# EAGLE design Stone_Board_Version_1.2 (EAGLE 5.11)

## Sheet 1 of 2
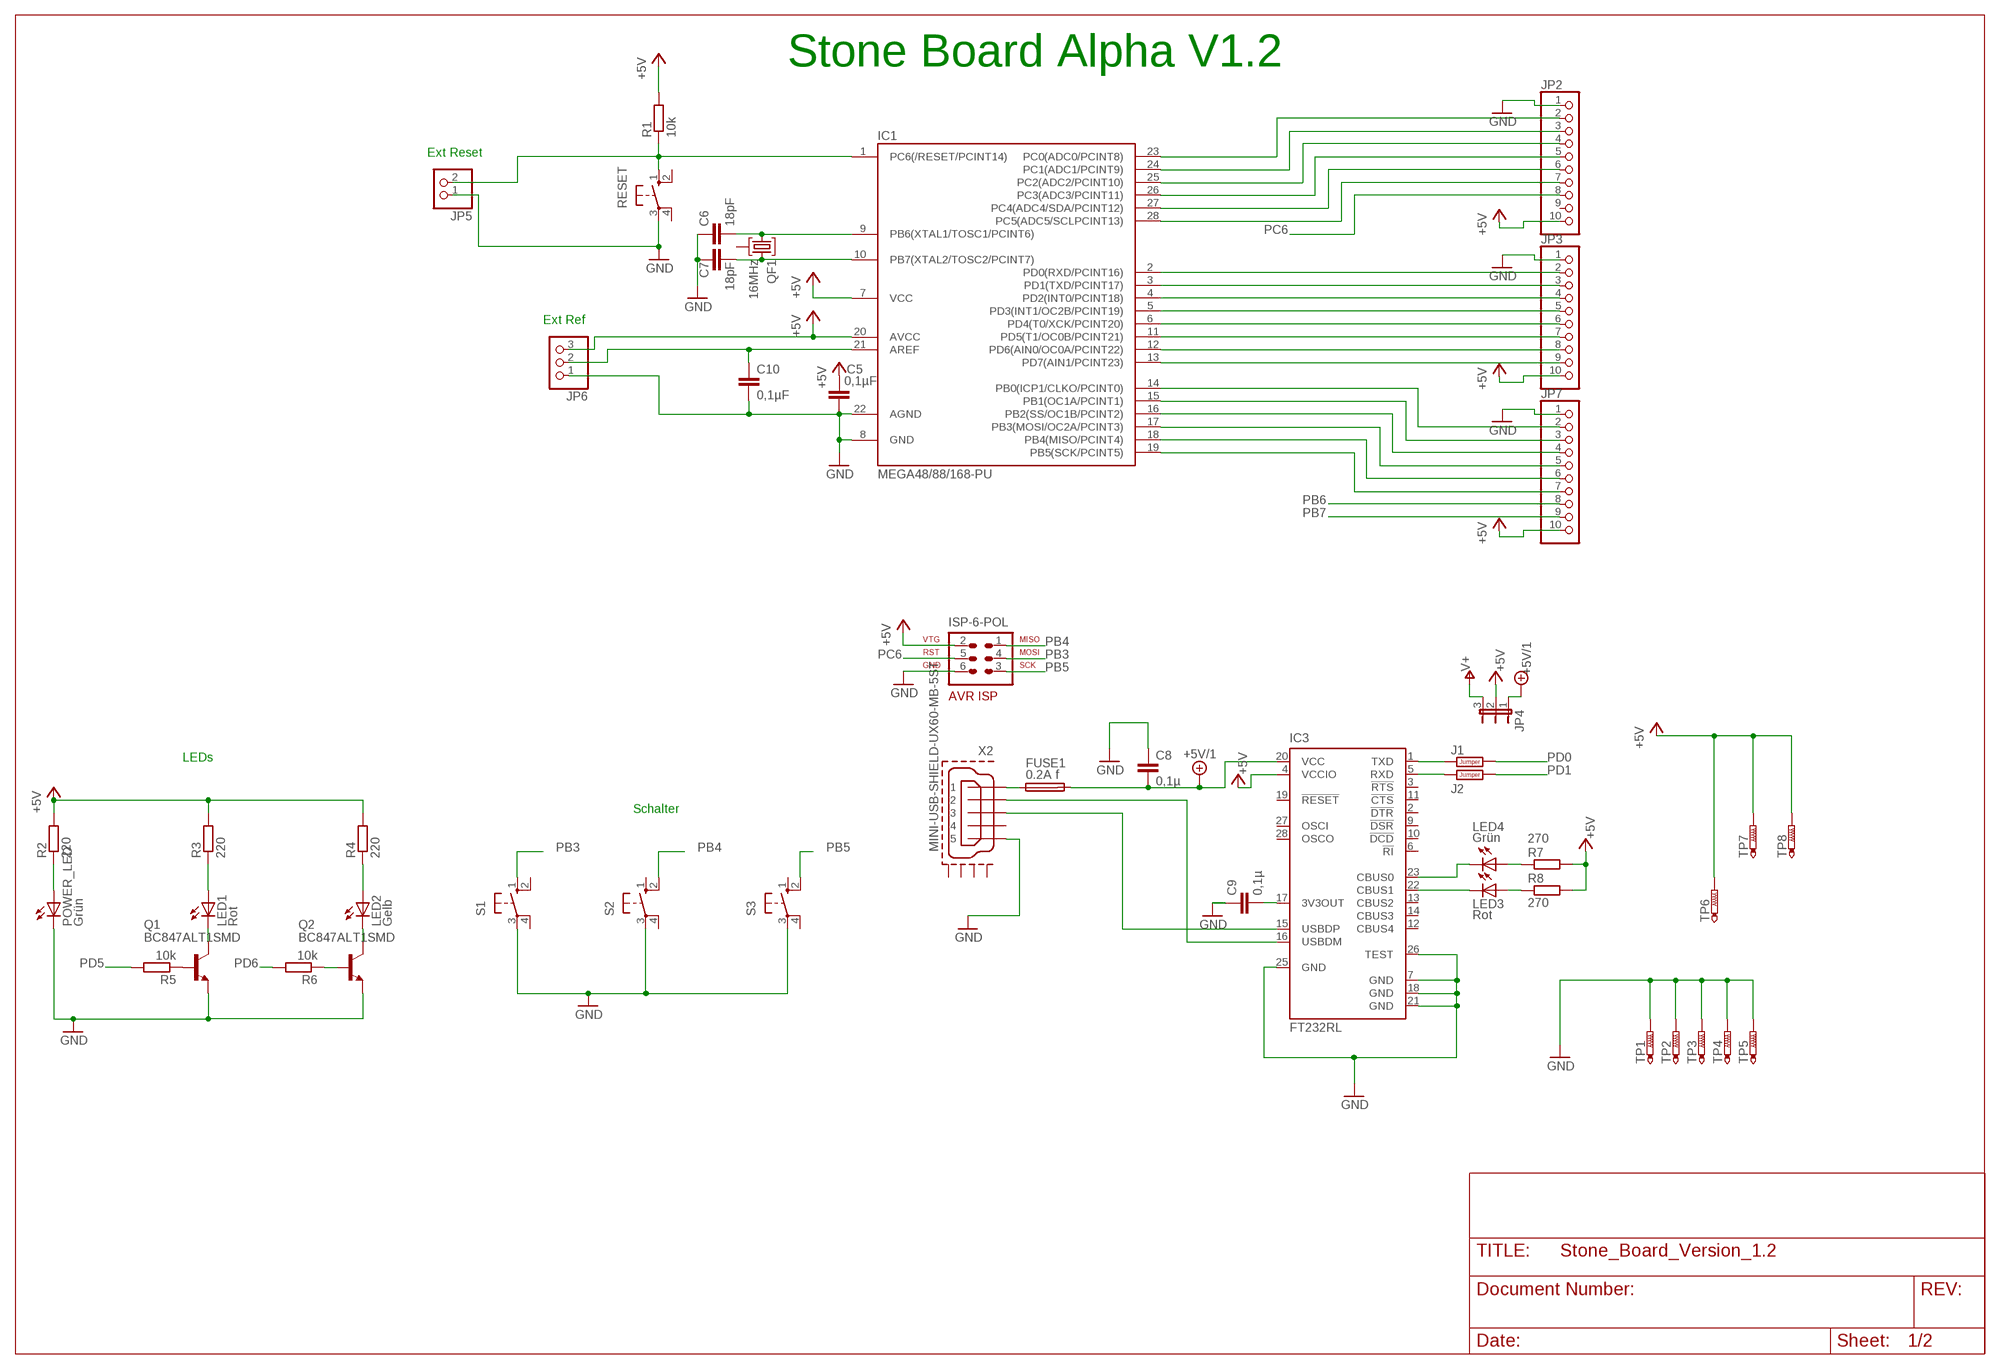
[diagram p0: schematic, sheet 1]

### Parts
C5  0,1µF  C-EU025-025X050  [C025-025X050]
C6  18pF  C-EU025-025X050  [C025-025X050]
C7  18pF  C-EU025-025X050  [C025-025X050]
C8  0,1µ  C-EU025-025X050  [C025-025X050]
C9  0,1µ  C-EU025-025X050  [C025-025X050]
C10  0,1µF  C-EU025-025X050  [C025-025X050]
FUSE1  0.2A f  SICHERUNG_1206  [1206]
IC1  MEGA48/88/168-PU  [DIL28-3]
IC3  FT232RL  [SSOP28]
ISP-6-POL  ISP-6-POL  [ISP-6-POL]
J1  CUTJUMPER  [CUTJUMPER]
J2  CUTJUMPER  [CUTJUMPER]
JP2  PINHD-1X10  [1X10]
JP3  PINHD-1X10  [1X10]
JP4  JP2E  [JP2]
JP5  PINHD-1X2  [1X02]
JP6  PINHD-1X3  [1X03]
JP7  PINHD-1X10  [1X10]
LED1  Rot  LEDCHIPLED_1206  [CHIPLED_1206]
LED2  Gelb  LEDCHIPLED_1206  [CHIPLED_1206]
LED3  Rot  LEDCHIPLED_1206  [CHIPLED_1206]
LED4  Grün  LEDCHIPLED_1206  [CHIPLED_1206]
POWER_LED  Grün  LEDCHIPLED_1206  [CHIPLED_1206]
Q1  BC847ALT1SMD  [SOT23]
Q2  BC847ALT1SMD  [SOT23]
QF1  16MHz  8M10AHC49T  [HC49U]
R1  10k  R-EU_M1206  [M1206]
R2  220  R-EU_M1206  [M1206]
R3  220  R-EU_M1206  [M1206]
R4  220  R-EU_M1206  [M1206]
R5  10k  R-EU_M1206  [M1206]
R6  10k  R-EU_M1206  [M1206]
R7  270  R-EU_R1206  [R1206]
R8  270  R-EU_R1206  [R1206]
RESET  10-XX  [B3F-10XX]
S1  10-XX  [B3F-10XX]
S2  10-XX  [B3F-10XX]
S3  10-XX  [B3F-10XX]
TP1  PTR1LÖTNAGEL0,8MM  [LN_0.8MM]
TP2  PTR1LÖTNAGEL0,8MM  [LN_0.8MM]
TP3  PTR1LÖTNAGEL0,8MM  [LN_0.8MM]
TP4  PTR1LÖTNAGEL0,8MM  [LN_0.8MM]
TP5  PTR1LÖTNAGEL0,8MM  [LN_0.8MM]
TP6  +5V  PTR1LÖTNAGEL0,8MM  [LN_0.8MM]
TP7  PTR1LÖTNAGEL0,8MM  [LN_0.8MM]
TP8  PTR1LÖTNAGEL0,8MM  [LN_0.8MM]
X2  MINI-USB-SHIELD-UX60-MB-5ST  [UX60-MB-5ST]

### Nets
+5V: C5.1 IC1.7(VCC) IC1.20(AVCC) IC3.4(VCCIO) ISP-6-POL.2 JP2.10 JP3.10 JP4.2 JP6.3 JP7.10 R1.2 R2.2 R3.2 R4.2 R7.2 R8.2 TP6.P$1(TP) TP7.P$1(TP) TP8.P$1(TP)
+5V/1: C8.2 FUSE1.2 IC3.20(VCC) JP4.1
AREF: C10.1 IC1.21(AREF) JP6.2
GND: C5.2 C6.1 C7.1 C8.1 C9.1 C10.2 IC1.8(GND) IC1.22(AGND) IC3.7(GND) IC3.18(GND) IC3.21(GND) IC3.25(GND) IC3.26(TEST) ISP-6-POL.6 JP2.1 JP3.1 JP5.1 JP6.1 JP7.1 POWER_LED.C Q1.2(E) Q2.2(E) RESET.3(P) S1.3(P) S2.3(P) S3.3(P) TP1.P$1(TP) TP2.P$1(TP) TP3.P$1(TP) TP4.P$1(TP) TP5.P$1(TP) X2.5 ; also sheet 2
N$2: IC3.1(TXD) J1.1
N$3: IC3.5(RXD) J2.1
N$4: LED4.A R7.1
N$5: LED3.A R8.1
N$6: IC3.23(CBUS0) LED4.C
N$7: IC3.22(CBUS1) LED3.C
N$12: POWER_LED.A R2.1
N$14: FUSE1.1 X2.1
N$15: IC3.16(USBDM) X2.2
N$16: IC3.15(USBDP) X2.3
N$17: LED1.A R3.1
N$18: C9.2 IC3.17(3V3OUT)
N$19: LED2.A R4.1
N$20: LED1.C Q1.3(C)
N$21: LED2.C Q2.3(C)
N$22: Q1.1(B) R5.1
N$23: Q2.1(B) R6.1
PB0: IC1.14(PB0(ICP1/CLKO/PCINT0)) JP7.2
PB1: IC1.15(PB1(OC1A/PCINT1)) JP7.3
PB2: IC1.16(PB2(SS/OC1B/PCINT2)) JP7.4
PB3: IC1.17(PB3(MOSI/OC2A/PCINT3)) ISP-6-POL.4 JP7.5 S1.1(S)
PB4: IC1.18(PB4(MISO/PCINT4)) ISP-6-POL.1 JP7.6 S2.2(S1)
PB5: IC1.19(PB5(SCK/PCINT5)) ISP-6-POL.3 JP7.7 S3.2(S1)
PB6: C6.2 IC1.9(PB6(XTAL1/TOSC1/PCINT6)) JP7.8 QF1.1
PB7: C7.2 IC1.10(PB7(XTAL2/TOSC2/PCINT7)) JP7.9 QF1.3
PC0: IC1.23(PC0(ADC0/PCINT8)) JP2.2
PC1: IC1.24(PC1(ADC1/PCINT9)) JP2.3
PC2: IC1.25(PC2(ADC2/PCINT10)) JP2.4
PC3: IC1.26(PC3(ADC3/PCINT11)) JP2.5
PC4: IC1.27(PC4(ADC4/SDA/PCINT12)) JP2.6
PC5: IC1.28(PC5(ADC5/SCLPCINT13)) JP2.7
PC6: IC1.1(PC6(/RESET/PCINT14)) ISP-6-POL.5 JP2.8 JP5.2 R1.1 RESET.1(S)
PD0: IC1.2(PD0(RXD/PCINT16)) J1.2 JP3.2
PD1: IC1.3(PD1(TXD/PCINT17)) J2.2 JP3.3
PD2: IC1.4(PD2(INT0/PCINT18)) JP3.4
PD3: IC1.5(PD3(INT1/OC2B/PCINT19)) JP3.5
PD4: IC1.6(PD4(T0/XCK/PCINT20)) JP3.6
PD5: IC1.11(PD5(T1/OC0B/PCINT21)) JP3.7 R5.2
PD6: IC1.12(PD6(AIN0/OC0A/PCINT22)) JP3.8 R6.2
PD7: IC1.13(PD7(AIN1/PCINT23)) JP3.9
V+: JP4.3 ; also sheet 2
Unconnected: IC3.2(!DTR) IC3.3(!RTS) IC3.6(!RI) IC3.9(!DSR) IC3.10(!DCD) IC3.11(!CTS) IC3.12(CBUS4) IC3.13(CBUS2) IC3.14(CBUS3) IC3.19(!RESET) IC3.27(OSCI) IC3.28(OSCO) JP2.9 QF1.2 RESET.2(S1) RESET.4(P1) S1.2(S1) S1.4(P1) S2.1(S) S2.4(P1) S3.1(S) S3.4(P1) X2.4 X2.M1(GND1) X2.M2(GND2) X2.M3(GND3) X2.M4(GND4)

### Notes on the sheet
- Stone Board Alpha V1.2
- Ext Reset
- Ext Ref
- LEDs
- Schalter

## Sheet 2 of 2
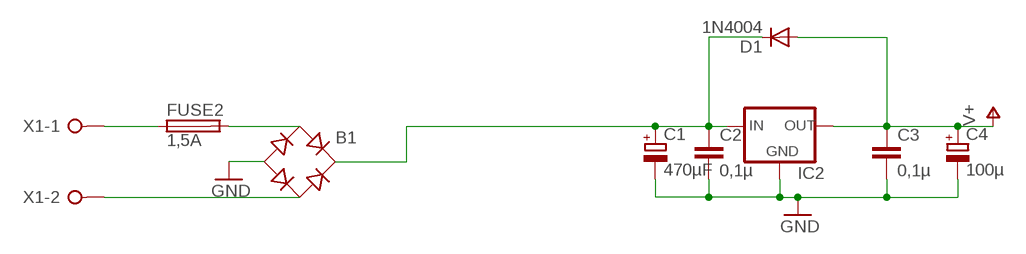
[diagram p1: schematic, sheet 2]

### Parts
B1  B-DIL  [B-DIL]
C1  470µF  CPOL-EUE3.5-8  [E3,5-8]
C2  0,1µ  C-EU025-025X050  [C025-025X050]
C3  0,1µ  C-EU025-025X050  [C025-025X050]
C4  100µ  CPOL-EUE2-5  [E2-5]
D1  1N4004  [DO41-10]
FUSE2  1,5A  SICHERUNG_1206  [1206]
IC2  78XXS  [78XXS]
X1  W237-02P  [W237-132]

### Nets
GND: B1.- C1.- C2.2 C3.2 C4.- IC2.GND ; also sheet 1
N$1: B1.+ C1.+ C2.1 D1.C IC2.IN
N$8: FUSE2.1 X1.1
N$9: B1.AC1 FUSE2.2
N$10: B1.AC2 X1.2
V+: C3.1 C4.+ D1.A IC2.OUT ; also sheet 1

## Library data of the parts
B1 = rectifier:B-DIL: RECTIFIER
C1 C4 = rcl:CPOL-EU: POLARIZED CAPACITOR, European symbol
C2 C3 C5-C10 = rcl:C-EU: CAPACITOR, European symbol
D1 = diode:1N4004: DIODE
FUSE1 FUSE2 = Eigene Eagle Bib:SICHERUNG_1206
IC1 = avr-6:MEGA48/88/168-PU
IC2 = v-reg:78XXS: VOLTAGE REGULATOR
IC3 = ftdichip:FT232R: Source: http://www.ftdichip.com/Documents/DataSheets/DS_FT232R_v104.pdf; MPN: FT232RL; OC_FARNELL: 1146032; OC_NEWARK: 91K9918
ISP-6-POL = Eigene Eagle Bib:ISP-6-POL
J1 J2 = Eigene Eagle Bib:CUTJUMPER
JP2 JP3 JP7 = pinhead:PINHD-1X10: PIN HEADER
JP4 = jumper:JP2E: JUMPER
JP5 = pinhead:PINHD-1X2: PIN HEADER
JP6 = pinhead:PINHD-1X3: PIN HEADER
LED1-LED4 POWER_LED = led:LED: LED
Q1 Q2 = transistor-npn:BC847*: NPN Transistor
QF1 = crystal:8M10AHC49T: Monolithic Crystal Filters Source: www.vanlong.com; OC_FARNELL: unknown; OC_NEWARK: unknown
R1-R8 = rcl:R-EU_: RESISTOR, European symbol
RESET S1-S3 = switch-omron:10-XX: OMRON SWITCH; MPN: B3F-1000; OC_FARNELL: 176432; OC_NEWARK: 36M3542
TP1-TP8 = testpad:PTR1: TEST PIN
X1 = con-wago-508:W237-02P: WAGO SREW CLAMP; OC_FARNELL: unknown; OC_NEWARK: unknown
X2 = usb_con-update:MINI-USB-SHIELD-: MINI USB Connector Source: http://www.hirose.co.jp/cataloge_hp/e24000019.pdf

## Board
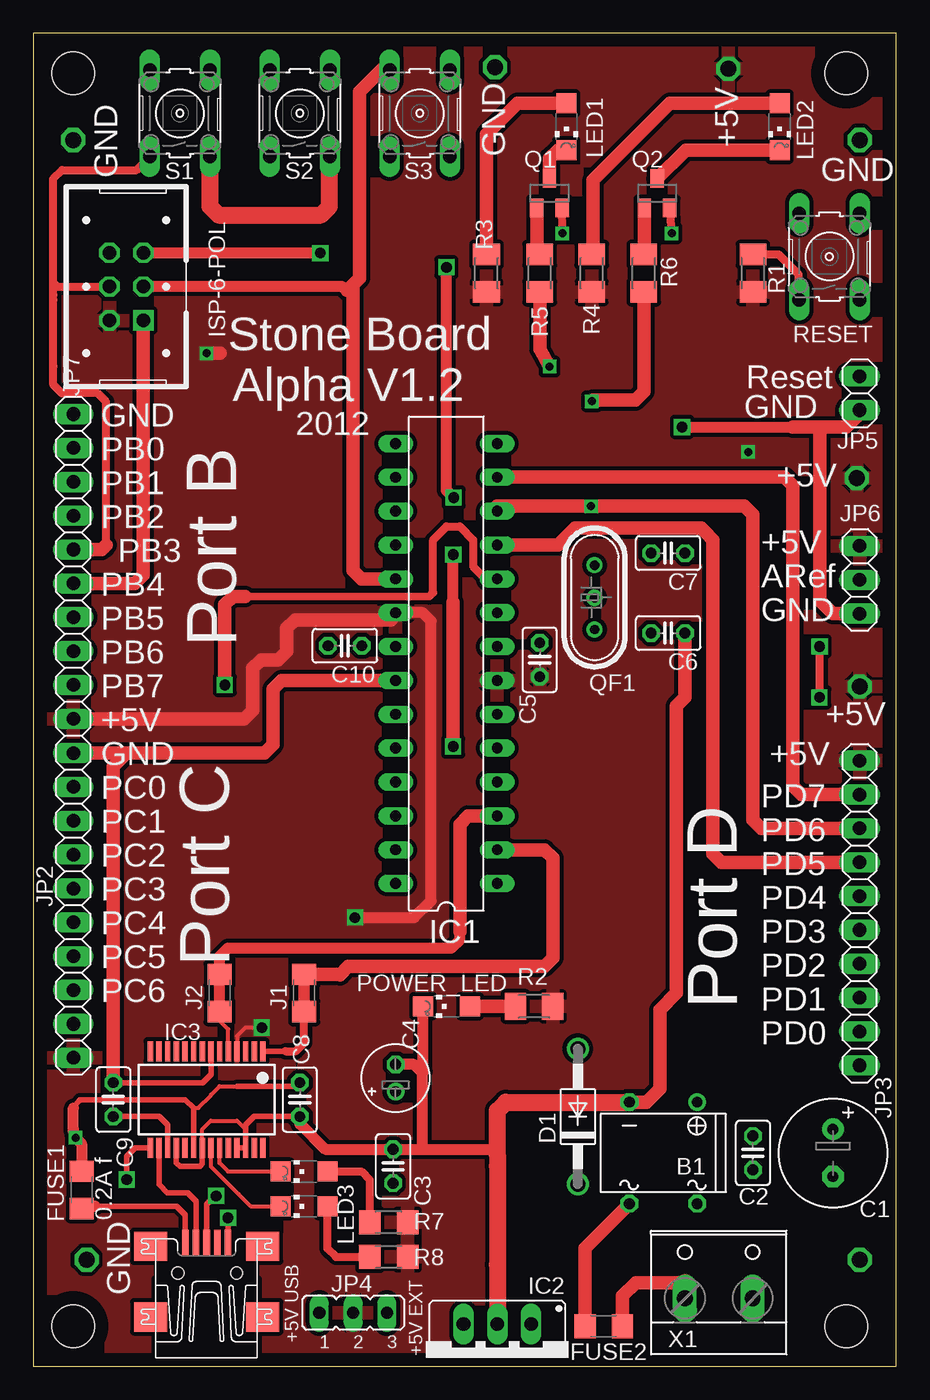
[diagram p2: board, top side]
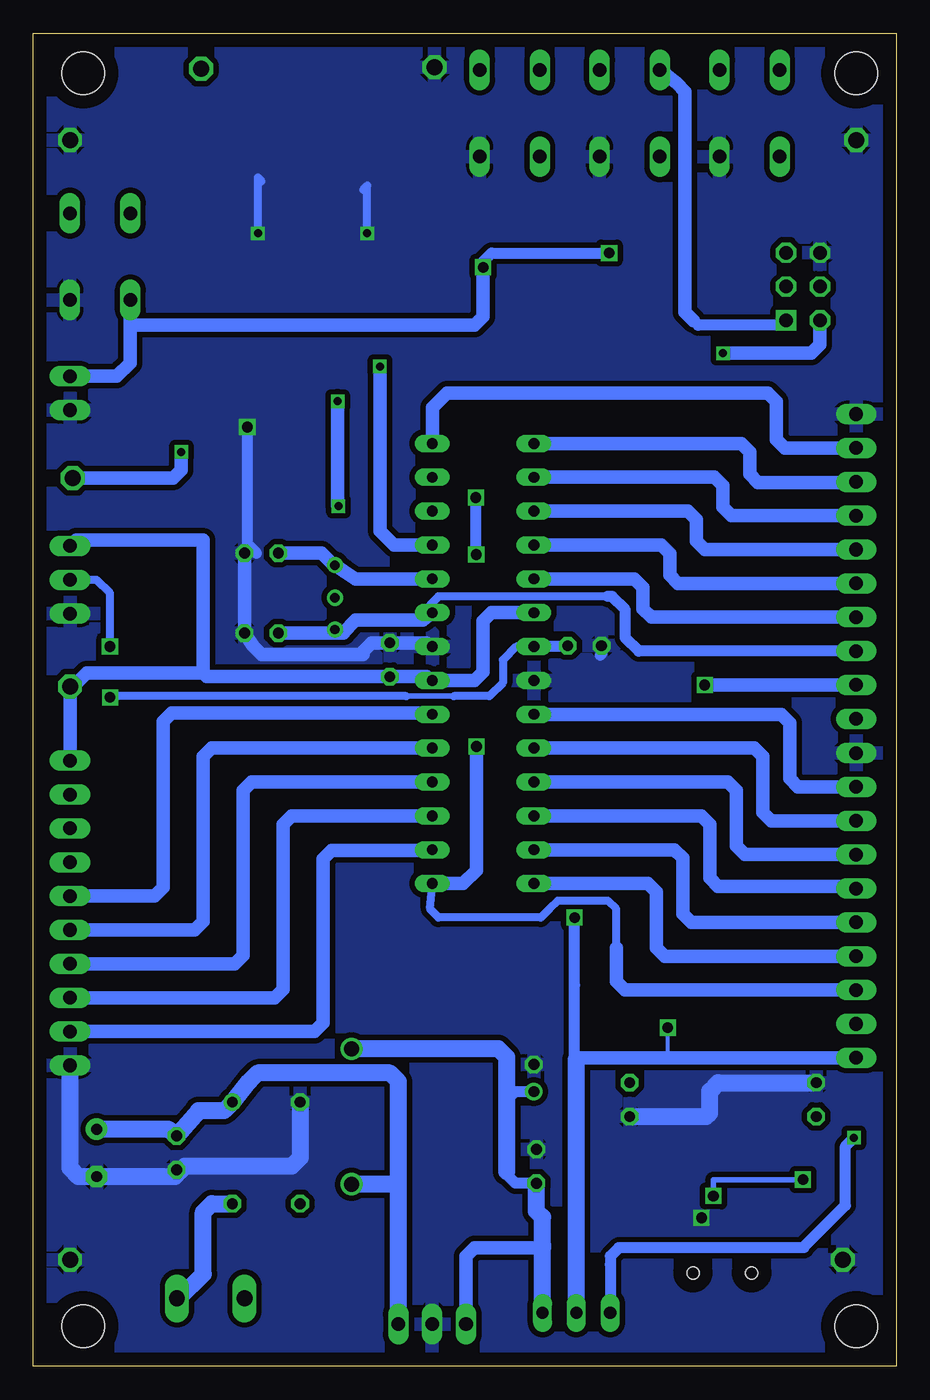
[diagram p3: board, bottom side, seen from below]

Size 64.75 x 100 mm. Coordinates in mm from the lower left corner, seen from the top.
Outline: 0,0 64.75,0 64.75,100 0,100 0,0
Copper layers (1*16): Top 0.035mm / dielectric 1.5mm / Bottom 0.035mm
Design rules "Bilex DRU": minimum track width 10mil, minimum drill 24mil, track to track 10mil, track to pad 10mil, pad to pad 10mil, via to via 10mil, smd to smd 10mil, copper to edge 40mil, drill to drill 8mil, minimum pad ring 10mil, minimum via ring 8mil, stop-mask expansion 4mil, vias tented up to drill 0mil, thermal gap 10mil
Holes 3.2 mm at 3,97 3,3 61,3 61,97

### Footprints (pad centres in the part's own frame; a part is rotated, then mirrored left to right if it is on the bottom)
B-DIL = drill 0.813 round: + -2.54,-3.81 | drill 0.813 octagon: - 2.54,-3.81; AC1 2.54,3.81; AC2 -2.54,3.81
E3,5-8 = drill 0.813 pad 1.6 round: + -1.778,0 | drill 0.813 pad 1.6 octagon: - 1.778,0
C025-025X050 = drill 0.813 octagon: 1 -1.27,0; 2 1.27,0
E2-5 = drill 0.813 pad 1.27 round: + -1.016,0 | drill 0.813 pad 1.27 octagon: - 1.016,0
DO41-10 = drill 1.118 round: A 5.08,0; C -5.08,0
1206 = smd 1.6 x 1.8: 1 -1.4,0; 2 1.4,0
DIL28-3 = drill 0.813 long: 1 -16.51,-3.81; 2 -13.97,-3.81; 3 -11.43,-3.81; 4 -8.89,-3.81; 5 -6.35,-3.81; 6 -3.81,-3.81; 7 -1.27,-3.81; 8 1.27,-3.81; 9 3.81,-3.81; 10 6.35,-3.81; 11 8.89,-3.81; 12 11.43,-3.81; 13 13.97,-3.81; 14 16.51,-3.81; 15 16.51,3.81; 16 13.97,3.81; 17 11.43,3.81; 18 8.89,3.81; 19 6.35,3.81; 20 3.81,3.81; 21 1.27,3.81; 22 -1.27,3.81; 23 -3.81,3.81; 24 -6.35,3.81; 25 -8.89,3.81; 26 -11.43,3.81; 27 -13.97,3.81; 28 -16.51,3.81
78XXS = drill 1.016 long: GND 0,-2.54; IN -2.54,-2.54; OUT 2.54,-2.54
SSOP28 = smd 0.4 x 1.5: 1 -4.225,-3.625; 2 -3.575,-3.625; 3 -2.925,-3.625; 4 -2.275,-3.625; 5 -1.625,-3.625; 6 -0.975,-3.625; 7 -0.325,-3.625; 8 0.325,-3.625; 9 0.975,-3.625; 10 1.625,-3.625; 11 2.275,-3.625; 12 2.925,-3.625; 13 3.575,-3.625; 14 4.225,-3.625; 15 4.225,3.625; 16 3.575,3.625; 17 2.925,3.625; 18 2.275,3.625; 19 1.625,3.625; 20 0.975,3.625; 21 0.325,3.625; 22 -0.325,3.625; 23 -0.975,3.625; 24 -1.625,3.625; 25 -2.275,3.625; 26 -2.925,3.625; 27 -3.575,3.625; 28 -4.225,3.625
ISP-6-POL = drill 1.016 square: 1 -2.54,-1.27 | drill 1.016 octagon: 2 -2.54,1.27; 3 0,-1.27; 4 0,1.27; 5 2.54,-1.27; 6 2.54,1.27
CUTJUMPER = smd 1.6 x 1.8: 1 -1.4,0; 2 1.4,0
1X10 = drill 1.016 long: 1 -11.43,0; 2 -8.89,0; 3 -6.35,0; 4 -3.81,0; 5 -1.27,0; 6 1.27,0; 7 3.81,0; 8 6.35,0; 9 8.89,0; 10 11.43,0
JP2 = drill 0.914 long: 1 -2.54,0; 2 0,0; 3 2.54,0
1X02 = drill 1.016 long: 1 -1.27,0; 2 1.27,0
1X03 = drill 1.016 long: 1 -2.54,0; 2 0,0; 3 2.54,0
CHIPLED_1206 = smd 1.5 x 1.5: A 0,-1.75; C 0,1.75
SOT23 = smd 1 x 1.4: 1 -0.95,-1.1; 2 0.95,-1.1; 3 0,1.1
HC49U = drill 0.7 pad 1.2 round: 1 -2.413,0; 2 -0.027,0; 3 2.413,0
M1206 = smd 1.6 x 2: 1 -1.4,0; 2 1.4,0
R1206 = smd 1.6 x 1.803: 1 -1.422,0; 2 1.422,0
B3F-10XX = drill 1.016 long: 1 -3.251,2.261; 2 3.251,2.261; 3 -3.251,-2.261; 4 3.251,-2.261
LN_0.8MM = drill 1.2 octagon: P$1 0,0
W237-132 = drill 1.194 long: 1 -2.54,-0.635; 2 2.54,-0.635
UX60-MB-5ST = smd 2 x 0.5: 1 2.25,1.6; 2 2.25,0.8; 3 2.25,0; 4 2.25,-0.8; 5 2.25,-1.6 | smd 2.2 x 2.5: M1 -3.3,-4.2; M2 -3.3,4.2; M3 2,4.2; M4 2,-4.2 | hole 0.9: 0,-2.25; 0,2.15

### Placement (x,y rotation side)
B1  47.27,16 180 top
C1  60,16 270 top
C2  54,16 270 top
C3  27,15 90 top
C4  27.19,21.62 90 top
C5  38,53 90 top
C6  47.63,55 180 top
C7  47.63,61 180 top
C8  20,20 90 top
C9  6,20 270 top
C10  23.38,54.05 180 top
D1  40.87,18.73 90 top
FUSE1  3.62,13.22 90 top
FUSE2  42.8,3 180 top
IC1  31,52.72 90 top
IC2  34.82,0.61 180 top
IC3  13,20 180 top
ISP-6-POL  6.99,81 90 top
J1  20.32,28 90 top
J2  13.97,28 90 top
JP2  3,34.57 270 top
JP3  62,34 90 top
JP4  24,4 0 top
JP5  62,73 90 top
JP6  62,59 90 top
JP7  3,60 270 top
LED1  40,93 180 top
LED2  56,93 180 top
LED3  20.32,12 90 top
LED4  20.32,14.61 90 top
POWER_LED  31,27 90 top
Q1  38.73,88 0 top
Q2  46.81,88 0 top
QF1  42.12,57.68 90 top
R1  54,82 270 top
R2  37.58,27 0 top
R3  34,82 270 top
R4  41.9,82 270 top
R5  38,82 270 top
R6  45.81,82 270 top
R7  26.67,10.79 0 top
R8  26.67,8.19 0 top
RESET  59.74,83.25 90 top
S1  11,94 90 top
S2  20,94 90 top
S3  29,94 90 top
TP1  62,8 0 top
TP2  4,8 0 top
TP3  3,92 0 top
TP4  62,92 0 top
TP5  34.63,97.44 0 top
TP6  62,51 0 top
TP7  52.16,97.33 0 top
TP8  61.79,66.61 0 top
X1  51.44,5.71 0 top
X2  13,7 90 top

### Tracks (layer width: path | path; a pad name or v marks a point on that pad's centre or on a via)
+5V  (via drill 0.6, 0.8)
  Top 0.305: IC3.4 15.28,24.77 15.91,25.4 v17.14,25.4
  Top 0.61: JP7.10 6.37,48.57
  Top 0.813: IC1.20 29.21,56.53 29.84,55.9 29.84,34.92 28.57,33.66 v24.13,33.66
  Top 1.016: IC1.20 26.83,56 19.64,56 19,55.37 19,53.63 18.36,53 17.09,53 16.46,52.37 16.46,49.2 15.82,48.57 JP7.10 | v13,76 14,76
  Bottom 0.305: 17.14,23.14 v17.14,25.4
  Bottom 0.813: 24,23 23.86,23.14 24.13,23.14 24.13,28.57 v24.13,33.66 | 5.72,78.09 ISP-6-POL.2
  Bottom 1.016: IC1.20 30.36,56.53 31,55.9 31,52.09 31.64,51.45 IC1.7 35.26,51.73 C5.1 51.73,51.73 52,52 | 23.86,23.14 17.14,23.14 JP2.10 | 52,52 52,62 61.54,62 JP6.3 | JP3.10 62,50.73 61,51.73 60.73,52 52,52 | TP8.P$1 54.27,66.61 53.64,67.25 v53.64,68.6 | 5.72,78.09 5.72,76.64 6.36,76 v13,76
  Bottom 1.27: JP4.2 24,23
  pour Top (isolate 0.305): 0,0 64,0 65,1 65,100 1,100 0,99
+5V/1  (via drill 0.6)
  Top 0.305: 15.28,21 13.97,21 13.34,20.36 13.34,20.32 12.38,19.36 12.03,19.36
  Top 0.406: 3,19.36 3.48,20 11.39,20 12.03,19.36 12.03,19 IC3.20 | C8.2 19.73,21 15.28,21
  Top 0.813: 3,19.36 3,17.78 3.1,17.25 v3.17,17.14 3.62,16.7 FUSE1.2
  Bottom 0.813: JP4.1 21.46,7.62 21.46,8.26 20.82,8.89 19.05,8.89 6.92,8.89 6.92,8.96 3.81,12.06 3.81,16.51 v3.17,17.14
AREF  (via drill 0.8)
  Top 0.61: v58.99,50.18 v59,50.19 v59,54
  Bottom 0.406: 33.2,50.27 36.77,50.27
  Bottom 0.61: IC1.21 28.52,53.99 29.52,52.99 29.52,51.27 30.52,50.27 33.2,50.27 | 36.77,50.27 58.9,50.27 v58.99,50.18 | v59,54 59,58 60,59 JP6.2
  Bottom 0.813: C10.1 24.71,53.99 IC1.21
GND  (via drill 0.6, 0.8)
  Top 0.305: IC3.21 12.68,17.78 13.31,18.41 13.34,18.41 15.29,18.41 15.93,17.78
  Top 0.406: X2.5 14.64,9.25 X2.5 v14.61,11.13 | IC3.21 12.68,15.18 12.5,15 11,15 10.72,15.28 IC3.18 | IC3.25 IC3.26 15.93,17.78 15.93,18.09 16.56,18.73 C8.1 20,18.18 | IC3.7 13.32,21.91 12.69,21.27 C9.1 | 47,20.81 47.31,21.12 | 34.42,16.27 34.82,15.88
  Top 0.61: 39.69,87.1 v39.69,85 39.69,87.1 | 47.75,87.05 v47.9,85 47.75,87.05 | 39.69,87.1 Q1.2 | 47.75,87.05 Q2.2
  Top 0.813: 20,18.18 21.91,16.27 C3.2 29.21,16.27 | v48.68,70.46 57,70.46 | 29.21,16.27 34.42,16.27 | C4.- 28.57,22.64 29.1,22.11 | 29.1,22.11 29.21,22 29.21,16.27 | POWER_LED.C 29.25,22.11 29.1,22.11
  Top 1.016: 7,46 JP2.1 | IC1.22 18.64,51.45 18,50.81 18,46.63 17.36,46 7,46 | JP5.1 62,71.46 61,70.46 59,70.46 | 57,70.46 59,70.46 | JP6.1 60,56.46 59,57.46 59,70.46 | 7,46 6,45 C9.1 | B1.- 46,19.81 47,20.81 47,25.4 47,26.73 48.27,28 48.26,49.53 48.91,50.17 C6.1
  Top 1.27: IC2.GND 34.82,7.62 34.82,15 34.82,15.88 34.82,19.18 35.45,19.81 B1.- | S1.3 13.26,87 13.9,86.36 21.59,86.36 22.23,87 22.23,90.17 22.26,90.13 S2.3
  Bottom 0.61: v39.69,85 39.69,88.58 40.01,88.27 | v47.9,85 47.9,89.17 47.62,88.9
  Bottom 0.813: v48.68,70.46 48.68,61.68 48,61 | C10.2 22.11,53.45 22.23,53.34
  Bottom 1.016: IC1.8 35.26,54.27 C5.2 39.37,54.27 40,53.63 40,53.4 47.63,53.4 48.27,54.03 C6.1 C7.1
  Bottom 1.27: B1.- 44.73,15.63 45.37,15 53.37,15 54,14.37 | 54,14.37 C2.2 | 54,14.37 54.14,14.22 C1.- 61.37,14.22 62,14.86 JP3.1 | C9.1 13.37,21.27 14,20.64 14,19 14.27,18.73 C8.1
  pour Bottom (isolate 0.406): 0,0 64,0 65,1 65,100 1,100 0,99
N$1
  Bottom 1.27: C1.+ 54.63,17.78 C2.1 52.35,19.18 50.45,19.18 B1.+ 48.54,21.36 47.91,22 37.99,22 37.36,21.36 37.36,13.34 | IC2.IN 37.36,8.89 | 37.36,8.89 37.36,11 37.36,13.34 | 37.36,8.89 37.36,9.1 | D1.C 37.67,13.65 37.36,13.34
N$2
  Top 0.406: IC3.1 18.92,23.62
  Top 0.61: 18.92,23.62 19.68,23.62 20.32,24.26 J1.1
N$3
  Top 0.305: J2.1 13.99,25.91 14.62,25.27 IC3.5
N$4
  Top 0.61: LED4.A 24.61,14.61 25.25,13.97 R7.1
N$5
  Top 0.61: LED3.A 22.07,8.82 22.7,8.19 R8.1
N$6
  Top 0.305: LED4.C 14.61,14.61 13.97,15.24 IC3.23
N$7
  Top 0.305: IC3.22 13.32,15.24 13.34,15.24 13.34,14.97 15.41,12.9 16.31,12 LED3.C
N$8
  Top 1.016: FUSE2.1 44.2,5.27 45.2,6.27 48.9,6.27
  Top 1.27: 48.9,6.27 X1.1
N$9
  Top 1.016: FUSE2.2 41.4,7.25 41.4,8.86 B1.AC1
N$10
  Bottom 1.016: 52.63,6.27 53.19,5.72
  Bottom 1.27: 52.09,6.82 52.63,6.27 | 52.09,6.82 52,6.91 52,11.55 51.37,12.19 B1.AC2 | X1.2 53.83,5.08 52.09,6.82
N$12
  Top 0.813: POWER_LED.A 32.75,27.25
  Top 1.016: POWER_LED.A R2.1
N$14
  Top 0.406: 4.63,12 10.77,12 11.4,11.37 X2.1
  Top 0.813: FUSE1.1 3.54,11.82 4.63,12
N$15
  Top 0.406: IC3.16 9.43,13.63 10.06,13 11.56,13 12.2,12.37 X2.2
N$16  (via drill 0.8)
  Top 0.406: IC3.15 7.63,16.38 7,15.74 v7,14 | v13.72,12.77 13.63,12.77 13,12.13 X2.3
  Bottom 0.406: v7,14 12.96,14 13.72,14 v13.72,12.77
N$17
  Top 1.016: R3.1 34,92.42 36.33,94.75 LED1.A
N$18
  Top 0.406: C9.2 9.44,18.73 10.07,18.09 IC3.17
N$19
  Top 1.016: LED2.A 47.75,94.75 42,89 42,83.5 R4.1
N$20
  Top 1.016: LED1.C 39.37,91.25 38.73,90.61 Q1.3
N$21
  Top 1.016: Q2.3 48.96,91.25 LED2.C
N$22
  Top 1.016: R5.1 37.78,83.61 Q1.1
N$23
  Top 1.016: R6.1 45.86,83.45 Q2.1
PB0
  Bottom 1.016: JP7.2 8.37,68.89 9,69.53 9,72.36 9.63,73 33.71,73 34.81,71.9 IC1.14
PB1
  Bottom 1.016: JP7.3 3.07,66.28 10.37,66.28 11,66.92 11,68.59 11.63,69.23 IC1.15
PB2
  Bottom 1.016: JP7.4 12.37,63.81 13,64.44 13,66.06 13.63,66.69 IC1.16
PB3
  Top 0.61: 1.5,80 1.5,75.01 1.5,73.64 2.13,73 4.83,73 5.46,72.36 5.46,61.59 5.46,61.27 | 1.5,80 1.5,80.36 | 1.5,80 1.5,81.28 | 1.5,81.28 1.5,89.11 2.13,89.75 7.74,89.75 S1.1 | ISP-6-POL.4 1.78,81 1.5,81.28
  Top 1.016: JP7.5 5.13,61.27 5.46,61.59
  Bottom 1.016: JP7.5 5.46,61.27 14.37,61.27 15,61.91 15,63.52 15.63,64.15 IC1.17
PB4
  Top 1.016: JP7.6 7.62,58.73 8.26,59.37 ISP-6-POL.1
  Bottom 0.813: 15.21,78.46 14.85,78.11 8.61,78.11 ISP-6-POL.1
  Bottom 1.016: JP7.6 16.36,58.73 17,59.37 17,60.98 17.64,61.61 19,61.61 IC1.18 | 15.21,78.46 15.84,79.09 15.84,95.62 16.48,96.25 S2.2
PB5
  Top 0.61: 24,80.86 23.86,81
  Top 0.813: 23.86,81 23.5,80.64 23.14,81 ISP-6-POL.3
  Top 1.016: 23.86,81 24.49,81.64 24.49,95.62 26.12,97.25 S3.2 | 24,80.86 24,59.69 24.62,59.07 IC1.19
  Bottom 1.016: JP7.7 18.36,56.19 19,56.83 19,58.44 19.64,59.07 23,59.07 24,59.07 IC1.19
PB6
  Bottom 0.61: IC1.9 34.98,57.12 34.34,57.76 21.64,57.76
  Bottom 0.813: JP7.8 19.32,53.65 20.32,54.65 20.32,56.52 20.32,56.76 21.32,57.76 21.64,57.76
  Bottom 1.016: IC1.9 35.51,56 40.59,56 41.52,54.99 QF1.1 41.49,55 C6.2
PB7  (via drill 0.8)
  Top 0.61: 15.63,57.76 15.88,57.76 29.71,57.77 29.72,57.76 30,58.04 30,62 31,63 32,63 33,62 33,60 33.93,59.07 IC1.10
  Top 1.016: v14.37,51.11 14.37,54.37 14.37,57.12 15,57.76 15.88,57.76
  Bottom 1.016: IC1.10 40.59,59.07 41.46,59.66 QF1.3 42.49,60.37 43.12,61 C7.2 | JP7.9 v14.37,51.11
PC0
  Bottom 1.016: JP2.2 7.37,43.46 8,44.09 8,48.27 8.63,48.91 IC1.23
PC1
  Bottom 1.016: JP2.3 9.37,40.92 10,41.55 10,45.73 10.63,46.37 IC1.24
PC2
  Bottom 1.016: JP2.4 11.37,38.38 12,39.02 12,43.2 12.63,43.83 IC1.25
PC3
  Bottom 1.016: JP2.5 3.16,36 13.37,36 14,36.63 14,40.66 14.63,41.29 IC1.26
PC4
  Bottom 1.016: JP2.6 15.37,33.3 16,33.94 16,38.12 16.64,38.75 IC1.27
PC5
  Bottom 1.016: JP2.7 17.36,30.76 18,31.39 18,35.58 18.64,36.21 IC1.28
PC6  (via drill 0.8)
  Top 0.61: R1.1 55.94,83.4 57.44,81.9 57.44,80.04 RESET.1
  Top 0.813: v21.54,83.52 8.18,83.52 8.26,83.44 ISP-6-POL.5 | v31,82.44 31,65.71 v31.54,65.17 | 31.51,57.29 v31.51,60.9
  Top 1.016: 31.51,57.29 31.5,57.28 v31.5,46.49 | 8.18,83.52 8.25,83.52
  Bottom 0.61: 21,31.36 21,34.29 21.64,34.92 24.13,34.92 25.4,34.92 26.04,34.29 26.67,33.66 34.34,33.66 34.98,34.29 IC1.1
  Bottom 0.813: v31,82.44 31,80 v31,82.44 | v31,82.44 31,82.89 30.36,83.52 v21.54,83.52 | v31.54,65.17 31.54,60.93 v31.51,60.9
  Bottom 1.016: JP2.8 20.36,28.22 21,28.86 21,31.36 | 31,80 | 57.48,78.11 57.48,75.56 57.48,75.27 58.48,74.27 JP5.2 | 57.48,78.11 RESET.1 | v31.5,46.49 31.5,37.21 32.5,36.21 IC1.1 | v31,82.44 31,78.73 31.64,78.12 57.48,78.11
PD0
  Top 0.61: 23.02,29.41 22.86,29.34 22.86,29.36
  Top 0.813: 22.86,29.36 23,29.36
  Top 1.016: 23,29.36 23.64,30 38.37,30 39,30.64 39,38.12 38.37,38.75 IC1.2 | J1.2 23.02,29.41
  Bottom 1.016: IC1.2 35.04,38.69 42.37,38.69 43,38.05 43,25.75 43.63,25.11 JP3.2
PD1
  Top 0.813: J2.2 13.97,30.73 14.61,31.36 31.36,31.36 32,32 32,32.17 32,32.63
  Top 1.016: 32,32.63 32,40.66 32.63,41.29 IC1.3
  Bottom 1.016: JP3.3 46.63,27.65 46,28.29 46,40.66 45.37,41.29 IC1.3
PD2
  Bottom 1.016: IC1.4 48.37,43.83 49,43.2 49,30.82 49.63,30.19 JP3.4
PD3
  Bottom 1.016: JP3.5 52.63,32.73 52,33.37 52,45.73 51.37,46.37 IC1.5
PD4
  Bottom 1.016: IC1.6 35.07,49 54.37,49 55,48.37 55,35.91 55.63,35.27 JP3.6
PD5  (via drill 0.6)
  Top 1.016: JP3.7 51.63,37.81 51,38.45 51,62 50.43,62.57 50.13,62.87 40.64,62.87 39.38,61.61 IC1.11 | v38.73,75 38,76.3 R5.2
  Bottom 1.016: v38.73,75 38.73,62.65 37.69,61.61 IC1.11
PD6  (via drill 0.6)
  Top 1.016: JP3.8 54.63,40.35 54,40.98 54,63.88 53.37,64.52 v41.85,64.52 34.81,64.52 IC1.12 | v41.91,72.39 42,72.48 45.17,72.48 45.81,73.11 R6.2
  Bottom 1.016: v41.85,64.52 41.91,64.58 v41.91,72.39
PD7
  Top 1.016: JP3.9 57.63,42.89 57,43.52 57,66.06 56.37,66.69 IC1.13
V+
  Bottom 0.813: C3.1 28.57,13.73 29.21,14.37 29.21,14.61 29.21,18.41 29.21,19.97 28.57,20.6 C4.+
  Bottom 1.016: 26.75,8.89 31.64,8.89 32.28,8.26 IC2.OUT
  Bottom 1.27: C3.1 27,11.63 26.54,11.18 26.54,9.1 | JP4.3 26.54,8.89 | 26.54,8.89 26.54,9.1 | 26.54,8.89 26.54,9.1 | 26.54,9.1 26.75,8.89 | D1.A 29.84,23.81 29.21,23.18 29.21,14.61

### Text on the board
tNames: GND | +5V | GND | GND | Stone Board | Reset | Alpha V1.2 | GND | GND | 2012 | PB0 | +5V | PB1 | PB2 | +5V | PB3 | PB4 | ARef | GND | PB5 | Port B | PB6 | PB7 | +5V | +5V | GND | +5V | PC0 | PD7 | PC1 | PD6 | PC2 | PD5 | PC3 | PD4 | PC4 | PD3 | PC5 | Port C | PD2 | PC6 | Port D | PD1 | PD0 | GND | +5V USB | +5V EXT
tValues: NC | +5V | GND | GND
